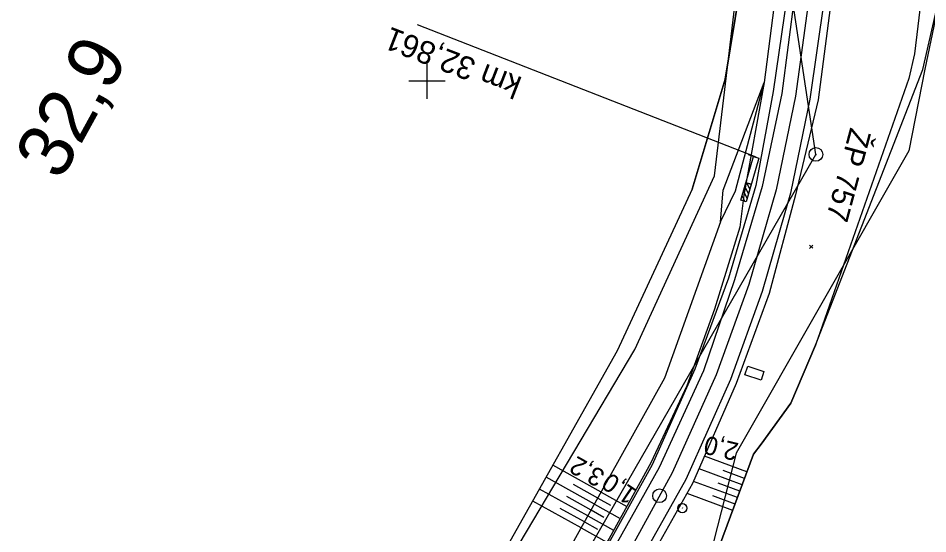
# Model space of a CAD drawing. Extents: x -804166 to -803706, y -1151030 to -1150147.
# Drawn here: x -803944.8 to -803845.1, y -1150649.7 to -1150593.1 of the extents above; entities that cross this region are included whole.
import ezdxf

# ---------------------------------------------------------------- set-up
doc = ezdxf.new("R2010")
doc.units = 0
for name, color, linetype in [('0381KM032-037P - Vrstva 1', 7, 'Continuous'), ('0381KM032-037P - Vrstva 17', 7, 'Continuous'), ('0381KM032-037P - Vrstva 4', 7, 'Continuous'), ('0381KM032-037P - Vrstva 48', 7, 'Continuous'), ('0381KM032-037P - Vrstva 49', 7, 'Continuous'), ('0381KM032-037P - Vrstva 50', 7, 'Continuous'), ('0381KM032-037P - Vrstva 51', 7, 'Continuous'), ('0381KM032-037P - Vrstva 6', 7, 'Continuous'), ('0381KM032-037P - Vrstva 7', 7, 'Continuous'), ('hran DP - hran DP', 7, 'Continuous'), ('krizky_1000 - Vrstva 1', 7, 'Continuous'), ('vyt_sit - polygon', 7, 'Continuous'), ('vyt_sit - stávající', 7, 'Continuous')]:
    doc.layers.add(name, color=color, linetype=linetype)

msp = doc.modelspace()

# ---------------------------------------------------------------- linework, layer by layer
at = {"layer": '0381KM032-037P - Vrstva 1'}
msp.add_lwpolyline([(-803862.645, -1150536.71), (-803860.057, -1150547.81), (-803858.364, -1150558.718), (-803857.51, -1150569.546), (-803857.425, -1150579.975), (-803858.096, -1150590.725), (-803859.58, -1150601.687), (-803861.73, -1150611.946), (-803864.691, -1150622.329), (-803868.306, -1150632.261), (-803873.118, -1150643.006), (-803878.784, -1150653.323), (-803884.455, -1150662.043), (-803890.68, -1150670.289), (-803894.474, -1150674.768)], dxfattribs=at)
at = {"layer": '0381KM032-037P - Vrstva 17'}
msp.add_lwpolyline([(-803867.911, -1150651.01), (-803864.194, -1150640.965), (-803863.34, -1150639.848), (-803860.107, -1150635.351), (-803857.384, -1150629.008), (-803845.634, -1150598.77), (-803839.769, -1150573.178), (-803837.289, -1150572.72)], dxfattribs=at)
at = {"layer": '0381KM032-037P - Vrstva 4'}
for points in [[(-803872.779, -1150506.875), (-803867.872, -1150516.171), (-803864.004, -1150525.679), (-803860.599, -1150536.286), (-803857.956, -1150547.888), (-803856.113, -1150558.65), (-803855.009, -1150569.422), (-803855.013, -1150580.14), (-803855.681, -1150591.137), (-803857.109, -1150602.102)], [(-803872.779, -1150506.875), (-803868.424, -1150516.34), (-803864.491, -1150525.922), (-803861.191, -1150536.397), (-803858.415, -1150547.949), (-803856.721, -1150558.765), (-803855.706, -1150569.464), (-803855.706, -1150580.041), (-803856.439, -1150591.045), (-803858.016, -1150602.009)], [(-803875.392, -1150508.511), (-803871.454, -1150517.68), (-803867.834, -1150527.236), (-803864.663, -1150537.291), (-803862.152, -1150548.382), (-803860.595, -1150558.999), (-803859.922, -1150569.628), (-803859.947, -1150579.801), (-803860.5, -1150590.58), (-803862.041, -1150601.171)], [(-803859.085, -1150579.867), (-803859.701, -1150590.693), (-803861.107, -1150601.386)], [(-803862.041, -1150601.171), (-803863.934, -1150611.478), (-803866.955, -1150621.666), (-803870.636, -1150631.623), (-803875.322, -1150642.112), (-803880.813, -1150652.073), (-803886.36, -1150660.761), (-803891.5, -1150667.581), (-803892.695, -1150669.921)], [(-803861.107, -1150601.386), (-803863.249, -1150611.592), (-803866.278, -1150621.841), (-803869.683, -1150631.826), (-803874.548, -1150642.393), (-803880.159, -1150652.477), (-803885.847, -1150661.208), (-803892.695, -1150669.921)], [(-803858.016, -1150602.009), (-803860.157, -1150612.315), (-803863.229, -1150623.106), (-803866.722, -1150632.775), (-803871.621, -1150643.742), (-803877.472, -1150654.13), (-803883.137, -1150662.978), (-803889.477, -1150671.458), (-803892.178, -1150675.246)], [(-803857.109, -1150602.102), (-803859.611, -1150612.518), (-803862.49, -1150623.34), (-803866.1, -1150633.182), (-803870.873, -1150644.181), (-803876.806, -1150654.687), (-803882.51, -1150663.405), (-803892.178, -1150675.246)]]:
    msp.add_lwpolyline(points, dxfattribs=at)
at = {"layer": '0381KM032-037P - Vrstva 48'}
for p, q in [((-803864.911, -1150642.902), (-803869.57, -1150641.178)), ((-803880.906, -1150645.106), (-803886.195, -1150642.162)), ((-803865.431, -1150644.309), (-803870.168, -1150642.556)), ((-803865.171, -1150643.606), (-803867.52, -1150642.736)), ((-803881.635, -1150646.417), (-803886.93, -1150643.47)), ((-803865.952, -1150645.716), (-803870.766, -1150643.934)), ((-803882.365, -1150647.727), (-803887.665, -1150644.777)), ((-803881.27, -1150645.761), (-803883.916, -1150644.289)), ((-803865.692, -1150645.012), (-803868.079, -1150644.129)), ((-803882, -1150647.072), (-803884.649, -1150645.598)), ((-803881.27, -1150645.76), (-803879.86, -1150646.545)), ((-803880.905, -1150645.105), (-803878.088, -1150646.673)), ((-803866.473, -1150647.123), (-803871.486, -1150645.267)), ((-803866.212, -1150646.419), (-803868.663, -1150645.512)), ((-803883.094, -1150649.038), (-803888.401, -1150646.085)), ((-803882.729, -1150648.383), (-803885.381, -1150646.907)), ((-803881.635, -1150646.416), (-803878.814, -1150647.986)), ((-803882.364, -1150647.726), (-803879.539, -1150649.299)), ((-803881.999, -1150647.071), (-803880.588, -1150647.857)), ((-803882.729, -1150648.382), (-803881.315, -1150649.168)), ((-803883.093, -1150649.037), (-803880.278, -1150650.604))]:
    msp.add_line(p, q, dxfattribs=at)
at = {"layer": '0381KM032-037P - Vrstva 49'}
for p, q in [((-803870.937, -1150611.902), (-803879.144, -1150629.624)), ((-803858.047, -1150618.024), (-803857.693, -1150618.376)), ((-803857.694, -1150618.023), (-803858.046, -1150618.377))]:
    msp.add_line(p, q, dxfattribs=at)
for points in [[(-803888.13, -1150522.065), (-803877.502, -1150535.708), (-803870.854, -1150543.675), (-803863.849, -1150556.524), (-803862.399, -1150570.315), (-803861.636, -1150589.369), (-803863.02, -1150600.178)], [(-803888.331, -1150532.703), (-803880.592, -1150540.151), (-803872.905, -1150546.743), (-803867.412, -1150556.856), (-803866.176, -1150570.896), (-803865.67, -1150589.811), (-803867.321, -1150599.808), (-803870.937, -1150611.902)], [(-803838.825, -1150566.88), (-803844.043, -1150574.496), (-803844.762, -1150582.145), (-803846.556, -1150597.039), (-803847.173, -1150599.748), (-803857.384, -1150629.008)], [(-803855.009, -1150569.422), (-803855.013, -1150580.14), (-803855.681, -1150591.137), (-803857.109, -1150602.102), (-803859.611, -1150612.518), (-803862.49, -1150623.34), (-803866.1, -1150633.182), (-803870.873, -1150644.181), (-803876.806, -1150654.687), (-803882.51, -1150663.405)], [(-803867.826, -1150615.469), (-803867.512, -1150611.999), (-803863.02, -1150600.178)], [(-803867.826, -1150615.469), (-803866.177, -1150612.082), (-803863.02, -1150600.178)], [(-803863.02, -1150600.178), (-803865.264, -1150612.536), (-803865.684, -1150616.069)], [(-803867.826, -1150615.469), (-803873.958, -1150632.621), (-803887.064, -1150656.172), (-803894.324, -1150662.675), (-803894.538, -1150670.386)], [(-803865.684, -1150616.069), (-803868.473, -1150625.045), (-803871.506, -1150633.468), (-803875.458, -1150641.91), (-803880.036, -1150650.199), (-803884.384, -1150657.469), (-803889.567, -1150664.922), (-803894.538, -1150670.386)], [(-803879.144, -1150629.624), (-803891.889, -1150652.288), (-803898.32, -1150663.448), (-803898.278, -1150667.796), (-803897.353, -1150671.802), (-803897.063, -1150673.395), (-803895.285, -1150678.85), (-803893.718, -1150680.524), (-803892.244, -1150682.081)], [(-803857.384, -1150629.008), (-803860.107, -1150635.351), (-803863.34, -1150639.848), (-803864.194, -1150640.965), (-803867.911, -1150651.01), (-803869.632, -1150654.159), (-803870.889, -1150656.426), (-803877.877, -1150667.643), (-803881.038, -1150676.732), (-803882.094, -1150681.238), (-803882.068, -1150682.623)]]:
    msp.add_lwpolyline(points, dxfattribs=at)
at = {"layer": '0381KM032-037P - Vrstva 50'}
for points in [[(-803870.937, -1150611.902), (-803867.321, -1150599.808), (-803865.67, -1150589.811), (-803866.176, -1150570.896), (-803867.412, -1150556.856), (-803872.905, -1150546.743), (-803880.592, -1150540.151), (-803888.331, -1150532.703), (-803894.19, -1150526.416), (-803900.653, -1150518.475)], [(-803870.937, -1150611.902), (-803879.144, -1150629.624), (-803891.889, -1150652.288), (-803898.32, -1150663.448), (-803898.278, -1150667.796), (-803897.353, -1150671.802), (-803897.063, -1150673.395)]]:
    msp.add_lwpolyline(points, dxfattribs=at)
at = {"layer": '0381KM032-037P - Vrstva 51'}
msp.add_lwpolyline([(-803863.373, -1150632.821), (-803865.148, -1150632.231), (-803864.816, -1150631.297), (-803863.081, -1150631.879), (-803863.373, -1150632.821)], dxfattribs=at)
at = {"layer": '0381KM032-037P - Vrstva 6'}
for p, q in [((-803863.898, -1150608.391), (-803901.037, -1150593.855)), ((-803864.186, -1150608.308), (-803864.763, -1150608.141)), ((-803865.153, -1150611.649), (-803864.743, -1150612.392)), ((-803864.444, -1150611.356), (-803865.02, -1150611.189)), ((-803864.97, -1150611.204), (-803864.596, -1150611.883)), ((-803864.46, -1150611.351), (-803864.448, -1150611.372)), ((-803864.444, -1150611.356), (-803864.444, -1150611.356)), ((-803865.448, -1150612.668), (-803865.133, -1150613.239)), ((-803865.3, -1150612.158), (-803864.891, -1150612.901))]:
    msp.add_line(p, q, dxfattribs=at)
msp.add_lwpolyline([(-803863.61, -1150608.474), (-803865, -1150613.277), (-803865.576, -1150613.111), (-803864.186, -1150608.308), (-803863.61, -1150608.474)], dxfattribs=at)
msp.add_lwpolyline([(-803865.576, -1150613.111), (-803865.02, -1150611.189), (-803864.444, -1150611.356), (-803865, -1150613.277)], close=True, dxfattribs=at)
at = {"layer": '0381KM032-037P - Vrstva 7'}
msp.add_line((-803871.973, -1150646.824), (-803872.021, -1150646.912), dxfattribs=at)
for centre, radius in [((-803874.49, -1150645.505), 0.75), ((-803871.997, -1150646.868), 0.5)]:
    msp.add_circle(centre, radius, dxfattribs=at)
at = {"layer": 'hran DP - hran DP'}
for p, q in [((-803868.49, -1150610.44), (-803863.95, -1150572.75)), ((-803842.82, -1150586.3), (-803845.41, -1150598.72)), ((-803845.41, -1150598.72), (-803847.18, -1150607.67)), ((-803847.18, -1150607.67), (-803866.11, -1150640.84)), ((-803877.2, -1150629.46), (-803868.49, -1150610.44)), ((-803894.67, -1150658.87), (-803877.2, -1150629.46)), ((-803866.11, -1150640.84), (-803869.51, -1150654.24))]:
    msp.add_line(p, q, dxfattribs=at)
at = {"layer": 'krizky_1000 - Vrstva 1'}
for points in [[(-803900, -1150598), (-803900, -1150602)], [(-803902, -1150600), (-803898, -1150600)]]:
    msp.add_lwpolyline(points, dxfattribs=at)
at = {"layer": 'vyt_sit - polygon'}
for p, q in [((-803857.351, -1150608.078), (-803872.981, -1150504.591)), ((-803907.43, -1150695.075), (-803857.351, -1150608.078))]:
    msp.add_line(p, q, dxfattribs=at)
at = {"layer": 'vyt_sit - stávající'}
msp.add_line((-803857.401, -1150608.078), (-803857.301, -1150608.078), dxfattribs=at)
msp.add_circle((-803857.351, -1150608.078), 0.756, dxfattribs=at)

# ---------------------------------------------------------------- texts
at = {"layer": '0381KM032-037P - Vrstva 48'}
for s, rotation, p in [('2,0', 166.54164, (-803865.72, -1150639.769)), ('3,2', 150.64897, (-803880.336, -1150642.91)), ('1,0', 145.90431, (-803876.829, -1150644.97))]:
    msp.add_text(s, height=2, rotation=rotation, dxfattribs=at).set_placement(p)
at = {"layer": '0381KM032-037P - Vrstva 6'}
msp.add_text('km 32,861', height=2.5, rotation=158.86045, dxfattribs=at).set_placement((-803889.433, -1150599.681))
at = {"layer": '0381KM032-037P - Vrstva 7'}
msp.add_text('32,9', height=6, rotation=61.22482, dxfattribs=at).set_placement((-803940.167, -1150611.093))
at = {"layer": 'vyt_sit - stávající'}
msp.add_text('ŽP 757', height=2.4, rotation=255, dxfattribs=at).set_placement((-803853.581, -1150605.05))

doc.saveas('drawing.dxf')
